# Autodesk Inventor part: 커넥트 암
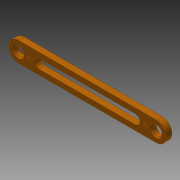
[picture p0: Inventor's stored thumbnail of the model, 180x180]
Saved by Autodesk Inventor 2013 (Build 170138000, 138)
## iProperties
Created: 2017-07
Part Number: 커넥트 암
Material: 스테인리스강
Document SubType Name: Modeling
Designer: mduedu
Density: 8.08 g/cm^3
Mass: 57.2031 g
Surface Area: 54.631 cm^2
Volume: 7.07959 cm^3
Author: mduedu
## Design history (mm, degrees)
sketch "스케치1"
  geometry: L1 (-67.5, 0)-(67.5, 0); L2 (-67.5, -8.5)-(67.5, -8.5); L3 (67.5, -8.5)-(67.5, 8.5); L4 (67.5, 8.5)-(-67.5, 8.5); L5 (-67.5, 8.5)-(-67.5, -8.5); L6 (-67.5, -8.5)-(67.5, 8.5); L7 (67.5, -8.5)-(-67.5, 8.5); 2 further points
  constraints: 14 end point, 4 midpoint, 2 horizontal, 2 parallel, 1 coincident, 1 perpendicular
  dimensions: "d0" = 135 distance of L1.start L1.end; "d2" = 17 distance of L2.end L3.end
extrude "돌출1" new body sketch "스케치1" distance "d3" = 5; taper "d4" = 0 deg
fillet "모깎기1"
fillet "모깎기2"
sketch "스케치2"
  geometry: C1 r 4 at (59, 0); A1 r 8.5 centre (59, 0) between (59, -8.5) and (59, 8.5) reference; 1 further point
  constraints: 1 centre point, 1 coincident
  dimensions: "d5" = 8 diameter of C1
extrude "돌출2" cut sketch "스케치2" stored distance "d6" = 10; taper "d7" = 0 deg
chamfer "모따기1" distance "d8" = 1; stored, may be unused: second distance "d9" = 2, angle "d10" = 45 deg
sketch "스케치3"
  geometry: L1 (-45, 0)-(45, 0); L2 (-45, -4)-(45, -4); L3 (45, -4)-(45, 4); L4 (45, 4)-(-45, 4); L5 (-45, 4)-(-45, -4); L6 (-45, -4)-(45, 4); L7 (45, -4)-(-45, 4); 2 further points
  constraints: 14 end point, 4 midpoint, 2 horizontal, 2 parallel, 1 coincident, 1 perpendicular
  dimensions: "d11" = 90 distance of L1.start L1.end; "d13" = 8 distance of L2.end L3.end
extrude "돌출3" cut sketch "스케치3" stored distance "d14" = 10; taper "d15" = 0 deg
fillet "모깎기3"
fillet "모깎기4"
sketch "스케치4"
  geometry: L1 (-59, 0)-(59, 0); C1 r 5 at (-59, 0) reference; C2 r 5 at (59, 0) reference; 3 further points
  constraints: 2 end point, 2 point on line, 1 horizontal, 2 other
  dimensions: "d16" = 50 distance of point (-50, 0) point (0, 0); "d17" = 50 distance of point (50, 0) point (0, 0)
feature "엠보싱1" sketch "스케치4" dims "d0" = 135, "d2" = 17, "d18" = 0.5, "d19" = 0
node "솔리드1"
mirror "대칭1"
